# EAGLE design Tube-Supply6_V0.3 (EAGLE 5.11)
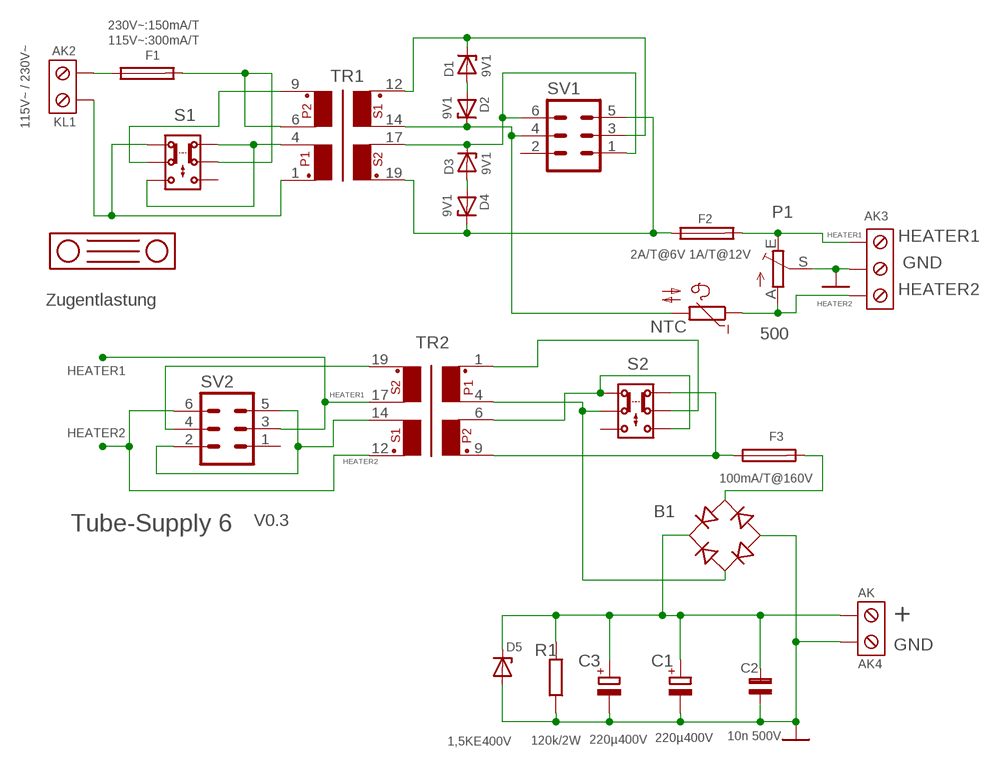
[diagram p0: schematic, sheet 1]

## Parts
AK  AK4  KL2RM7,5  [KL2RM7,5]
AK2  KL1  KLEMME2RM5  [KLEMME2]
AK3  KLEMME3STANDART  [KLEMME3]
B1  1000V/1A  DBL209G  [DB]
C1  220µ400V  CPOL-EUE10-25  [EB25D]
C2  10n 500V  C5B4,5E  [C5B4,5A]
C3  220µ400V  CPOL-EUE10-25  [EB25D]
D1  9V1  1N5333  [C1702-15]
D2  9V1  1N5333  [C1702-15]
D3  9V1  1N5333  [C1702-15]
D4  9V1  1N5333  [C1702-15]
D5  1,5KE400V  1N5333  [C1702-15]
F1  230V~:150mA/T  SH22,5A  [SH22,5A]
F2  2A/T@6V 1A/T@12V  SH22,5A  [SH22,5A]
F3  100mA/T@160V  SH22,5A  [SH22,5A]
NTC  NTC644B  [N644B]
P1  500  TRIM_EU-LI15  [LI15]
R1  120k/2W  R-EU_0411/12  [0411/12]
S1  X2200  [X2200]
S2  X2200  [X2200]
SV1  MA03-2  [MA03-2]
SV2  MA03-2  [MA03-2]
TR1  2x115V / 2x6V-2x2.5A  UI39X17DS45057  [UI39_24VA]
TR2  2x115V / 2x6V-2x2.5A  UI39X17DS45057  [UI39_24VA]
U$2  KAZU0442  [KAZU0442]

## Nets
+: AK.1 B1.+ C1.+ C2.2 C3.+ D5.C R1.2
GND: AK3.2 AK.2 B1.- C1.- C2.1 C3.- D5.A P1.S R1.1
HEATER1: AK3.3 F2.2 P1.E SV2.3 TR2.17
HEATER2: AK3.1 NTC.1 P1.A SV2.6 TR2.12
N$1: D3.A D4.A
N$3: D1.A D2.A
N$4: AK2.1 F1.1
N$5: F1.2 S1.1.2 TR1.6
N$6: S1.2.2 TR1.9
N$7: D1.C SV1.3 TR1.12
N$8: D2.C NTC.2 SV1.4 TR1.14
N$10: D4.C F2.1 SV1.5 TR1.19
N$11: D3.C SV1.1 SV1.6 TR1.17
N$12: SV2.4 TR2.19
N$13: SV2.2 SV2.5 TR2.14
N$17: B1.AC2 F3.2
N$18: AK2.2 S1.2.1 TR1.1
N$24: S1.1.1 S1.2.3 TR1.4
P1_1: S2.1.2 TR2.1
P1_4: B1.AC1 S2.2.2 TR2.4
P2_6: S2.1.3 S2.2.1 TR2.6
P2_9: F3.1 S2.1.1 TR2.9
Unconnected: S1.1.3 S2.2.3 SV1.2 SV2.1

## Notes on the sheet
- 115V~:300mA/T
- 115V~ / 230V~
- Zugentlastung
- V0.3
- Tube-Supply 6

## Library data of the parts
AK = VERBINDE:KL2RM7,5
AK2 = VERBINDE:KLEMME2
AK3 = VERBINDE:KLEMME3
B1 = rectifier:DB?*G: Single Phase 1.0 AMP Glass Passivated Bridge Rectifier Taiwan Semiconductor Co.,Ltd. - TSC Source: http://www.taiwansemi.com/TSCbig5/ezcatfiles/cust/img/img/db101g.pdf http://www.ts.com.tw/db/pictures/modules/PDT/PDT060207001/DBLS201G.pdf
C1 C3 = rcl:CPOL-EU: POLARIZED CAPACITOR, European symbol
C2 = CAP-Kondensatoren:C5B4,5E
D1-D5 = diode:1N5333: Z DIODE
F1-F3 = fuse:SH22,5A: FUSE HOLDER; MPN: 0031.7701.11; OC_FARNELL: unknown; OC_NEWARK: 04F1224
NTC = ptc-ntc:NTC644B: PHILIPS NTC; OC_FARNELL: unknown; OC_NEWARK: unknown
P1 = Potentiometer:TRIM_EU-: POTENTIOMETER
R1 = rcl:R-EU_: RESISTOR, European symbol
S1 S2 = switch:X2200
SV1 SV2 = con-lstb:MA03-2: PIN HEADER; OC_FARNELL: unknown; OC_NEWARK: unknown
TR1 TR2 = trafo:UI39X17DS45057
U$2 = MB:KAZU0442

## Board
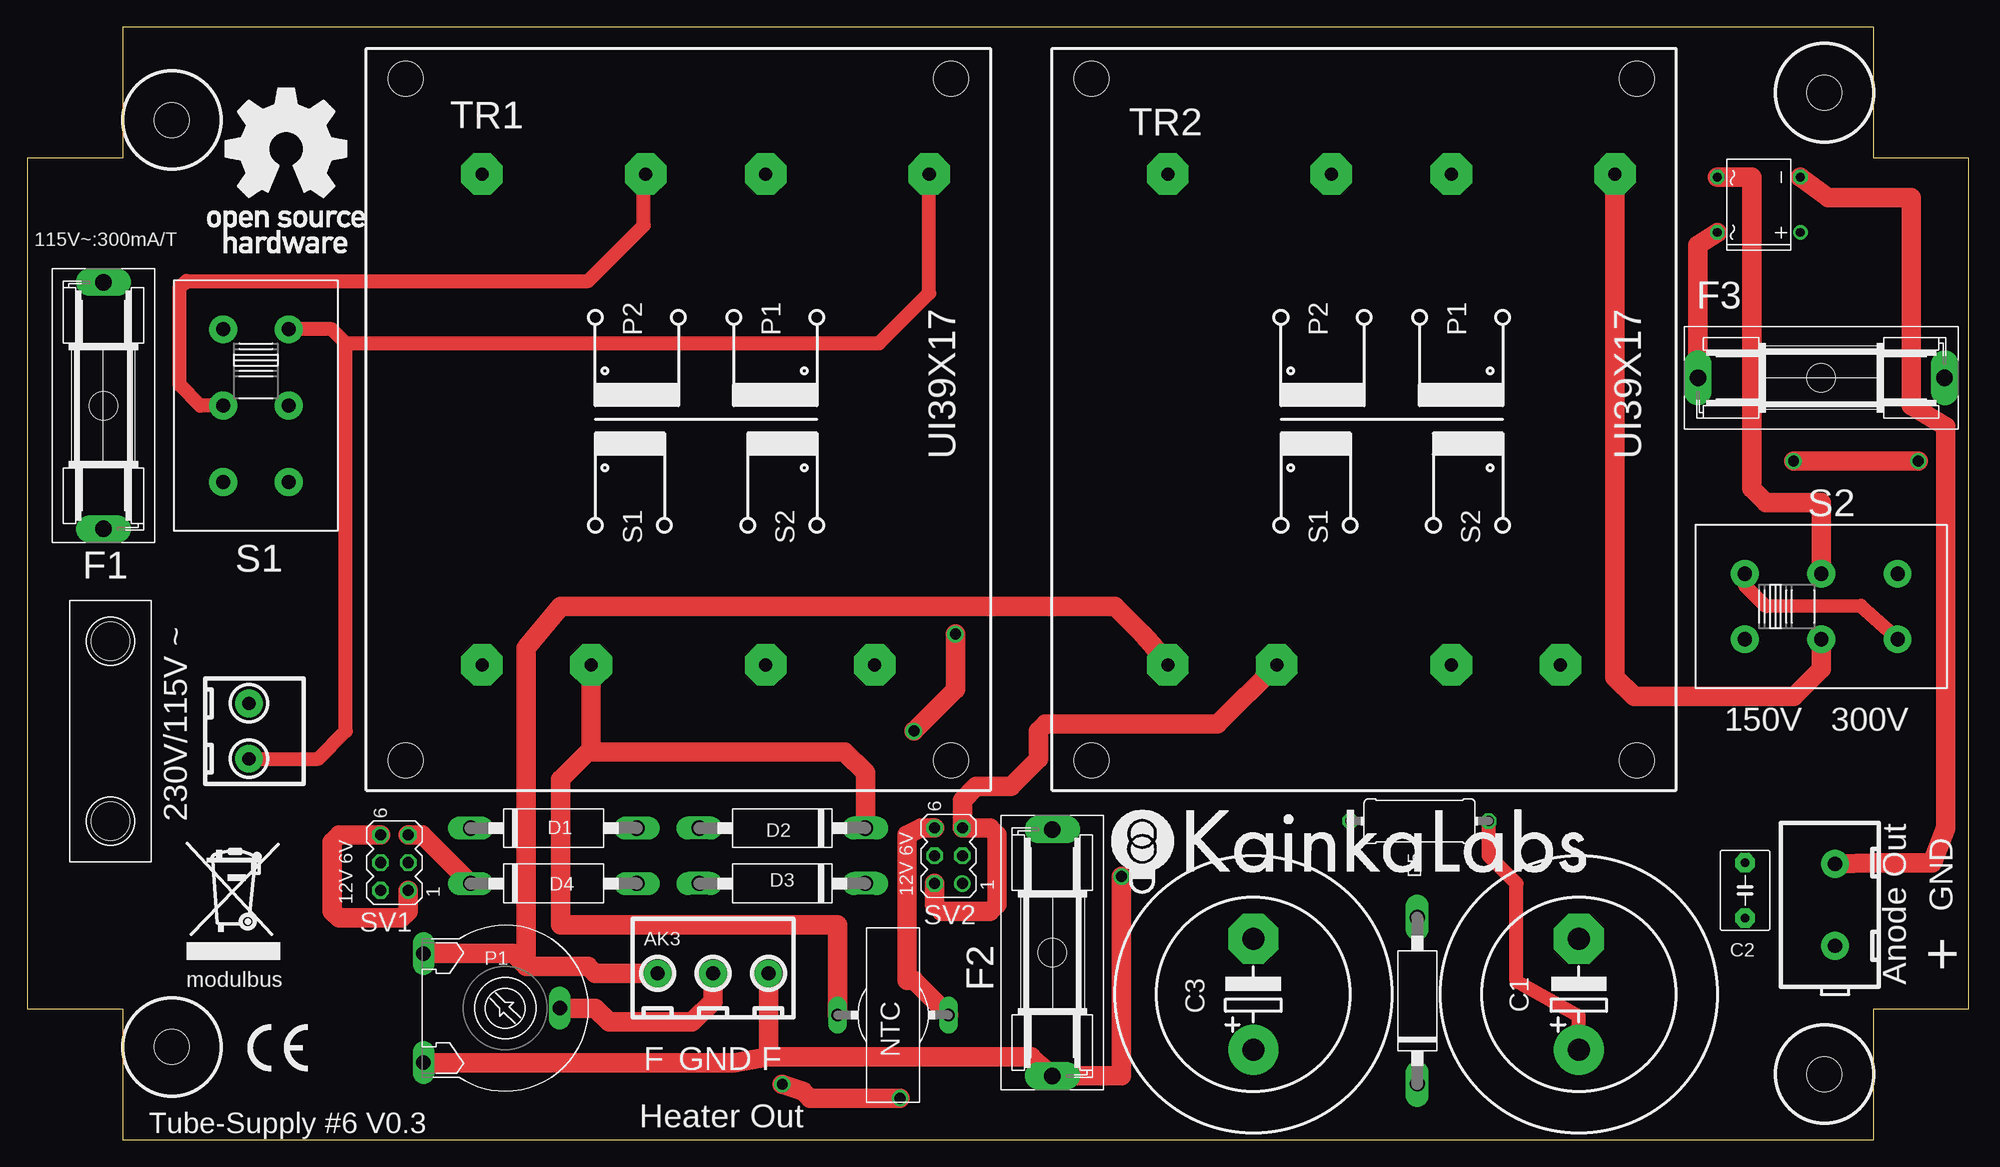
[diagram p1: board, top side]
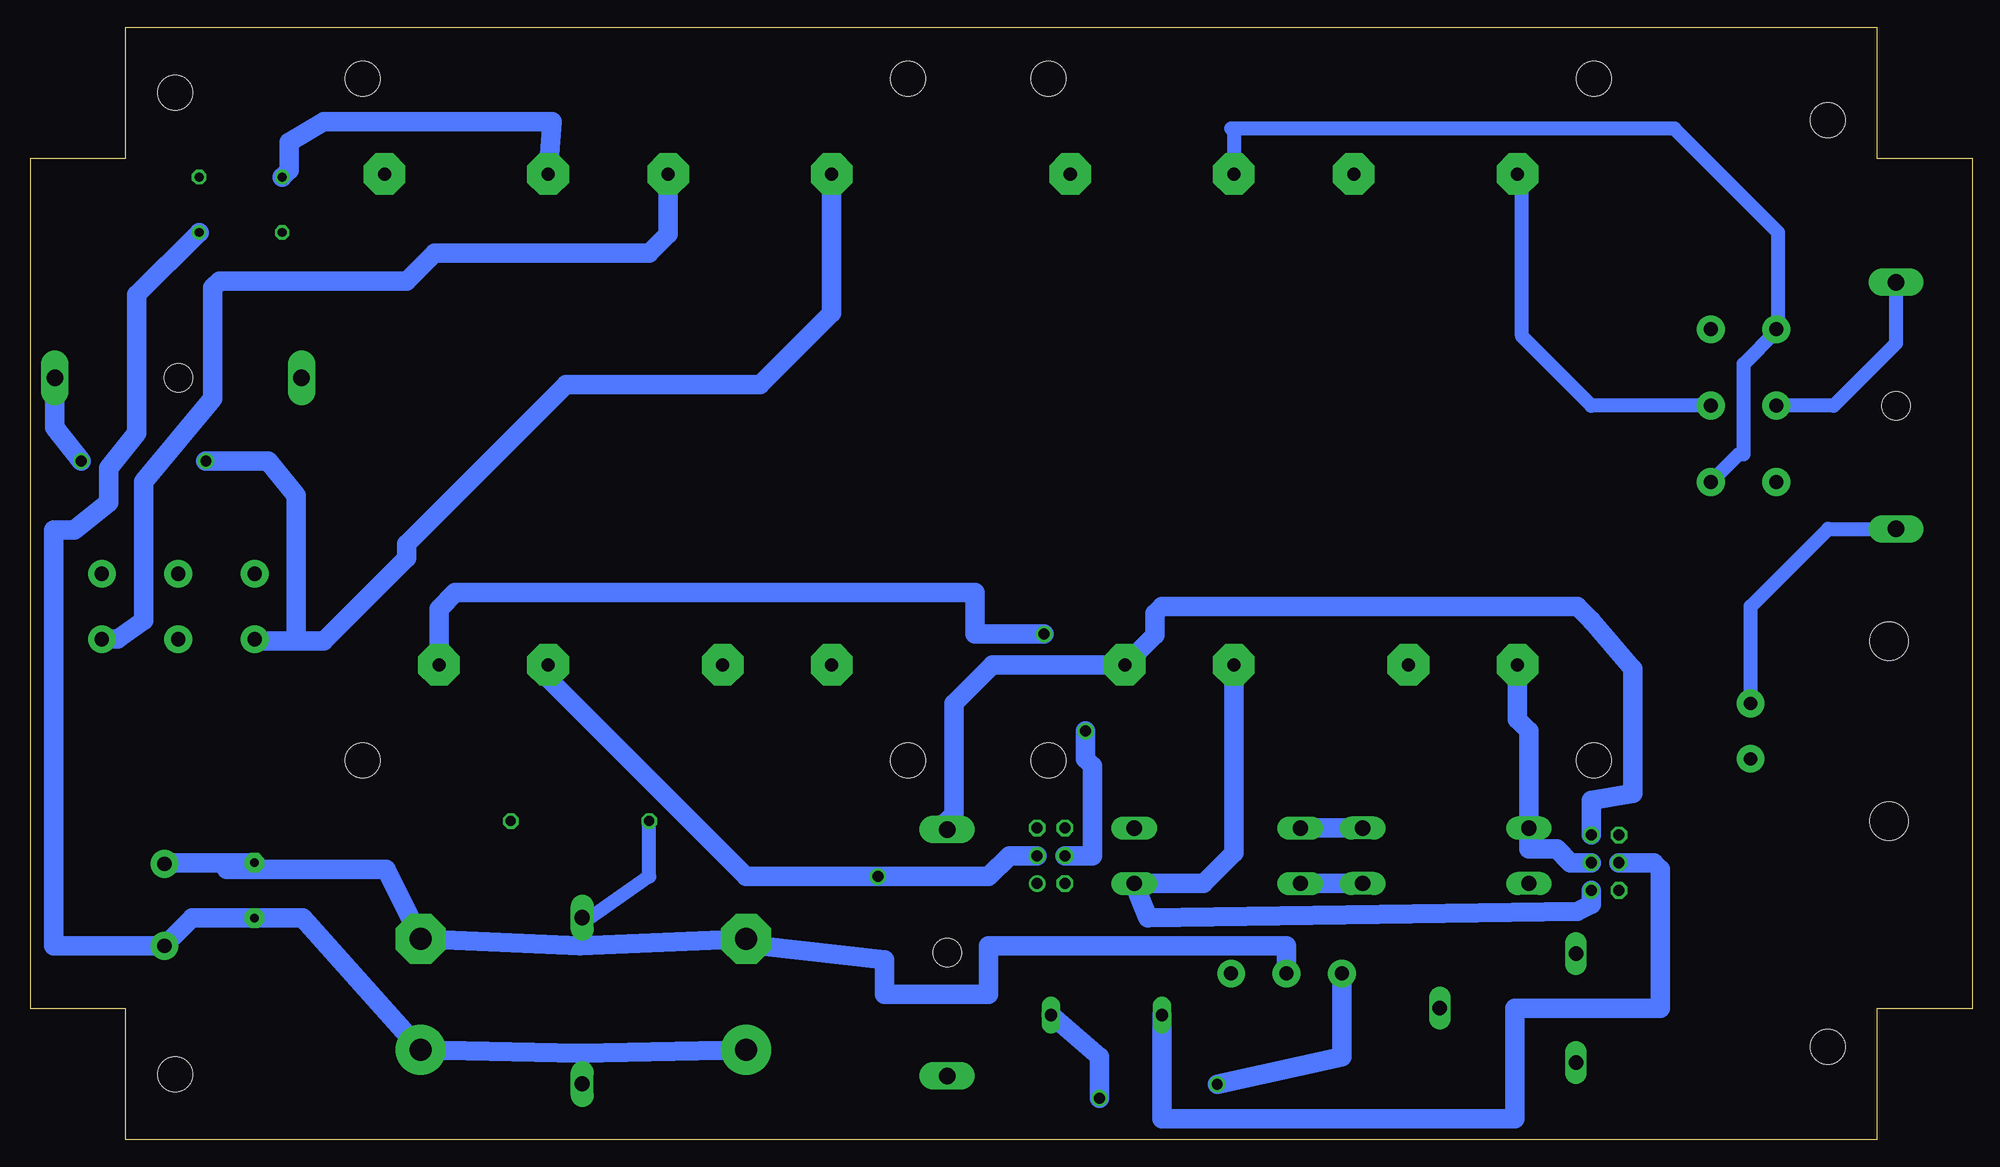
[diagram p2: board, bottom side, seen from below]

Size 178 x 102 mm. Coordinates in mm from the lower left corner, seen from the top.
Copper layers (1*16): Top 0.035mm / dielectric 1.5mm / Bottom 0.035mm
Design rules "default": minimum track width 10mil, minimum drill 23mil, track to track 8mil, track to pad 8mil, pad to pad 8mil, via to via 8mil, smd to smd 8mil, copper to edge 40mil, drill to drill 8mil, minimum pad ring 10mil, minimum via ring 8mil, stop-mask expansion 4mil, vias tented up to drill 0mil, thermal gap 20mil

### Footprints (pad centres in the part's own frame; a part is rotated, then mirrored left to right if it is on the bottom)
KL2RM7,5 = drill 1.3 pad 2.54 round: 1 0,0; 2 7.5,0
KLEMME2 = drill 1.2 pad 2.54 round: 1 0,0; 2 5.08,0
KLEMME3 = drill 1.3 pad 2.54 round: 1 0,0; 2 5.08,0; 3 10.16,0
DB = drill 0.813 round: + -2.54,-3.81 | drill 0.813 octagon: - 2.54,-3.81; AC1 2.54,3.81; AC2 -2.54,3.81
EB25D = drill 2.007 pad 4.597 round: + -5.08,0 | drill 2.007 pad 4.597 octagon: - 5.08,0
C5B4,5A = drill 0.813 pad 1.778 octagon: 1 -2.54,0; 2 2.54,0
C1702-15 = drill 1.397 long: A 7.62,0; C -7.62,0
SH22,5A = drill 1.5 pad 2.54 long: 1 -11.3,0; 2 11.3,0 | hole 2.6: 0,0
BO-E450 = hole 3.2: 13.25,8.5; 164.75,6; 13.25,93.5; 164.75,96
N644B = drill 1.118 long: 1 -5.08,0; 2 5.08,0
LI15 = drill 1.321 long: A -5,-7.5; E 5,-7.5; S 0,5
0411/12 = drill 0.914 octagon: 1 -6.35,0; 2 6.35,0
X2200 = drill 1.3 pad 2.54 round: 1.1 -7,-3; 1.2 0,-3; 1.3 7,-3; 2.1 -7,3; 2.2 0,3; 2.3 7,3
MA03-2 = drill 1.016 round: 1 -2.54,-1.27 | drill 1.016 octagon: 2 -2.54,1.27; 3 0,-1.27; 4 0,1.27; 5 2.54,-1.27; 6 2.54,1.27
UI39_24VA = drill 1.194 pad 3.81 octagon: 1 23,22.5; 4 8,22.5; 6 -3,22.5; 9 -18,22.5; 12 -18,-22.5; 14 -8,-22.5; 17 8,-22.5; 19 18,-22.5 | hole 3.2: -25,31.25; 25,31.25; 25,-31.25; -25,-31.25
KAZU0442 = hole 3.5: 0,0; 16.5,0

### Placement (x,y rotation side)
AK  165.74,17.78 90 top
AK2  20.32,40.01 270 top
AK3  57.78,15.24 0 top
B1  158.75,85.72 90 top
C1  142.24,13.34 90 top
C2  157.48,22.86 270 top
C3  112.39,13.34 90 top
D1  48.26,28.57 0 top
D2  69.22,28.57 180 top
D3  69.22,23.5 180 top
D4  48.26,23.5 0 top
D5  127.44,12.73 90 top
F1  6.99,67.31 90 top
F2  93.98,17.14 270 top
F3  164.47,69.85 180 top
GEHÄUSE  [BO-E450]  0,0 0 top
NTC  79.38,11.43 180 top
P1  43.81,12.06 270 top
R1  127.64,29.21 0 top
S1  20.95,67.31 270 top
S2  164.47,48.9 0 top
SV1  33.66,25.4 90 top
SV2  84.45,26.04 90 top
TR1  59.69,66.04 0 top
TR2  122.56,66.04 0 top
U$2  7.62,29.21 90 top
U$3  [KAINKALABS40MM]  99.36,22.55 0 top
U$4  [OSH15MM]  16.51,81.28 0 top
U$5  [EAR]  14.64,16.51 0 top
U$8  [CE6MM]  20.2,6.27 0 top

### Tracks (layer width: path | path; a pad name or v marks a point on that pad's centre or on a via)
+
  Top 1.27: R1.2 133.99,26.04 136.53,23.5 136.53,14.5 142.23,11.34 142.15,8.16 C1.+
  Bottom 1.27: D5.C 127.44,7.77 127.61,7.94
  Bottom 1.778: B1.+ 168.28,77.47 168.28,64.77 170.81,61.59 170.81,58.42 173.99,55.88 175.9,55.88 175.9,17.78 AK.1 163.19,20.32 C2.2 153.03,20.32 C1.+ 127.61,7.94 C3.+
GND
  Top 1.778: P1.S 52.07,12.06 53.34,10.79 60.96,10.79 62.87,12.7 AK3.2 | B1.- 165.1,86.36 172.72,86.36 172.72,67.31 175.9,65.41 175.9,28.57 174.62,25.4 169.43,25.4 AK.2
  Bottom 1.27: R1.1 121.28,24.13 127.64,19.68 | 127.64,19.68 127.64,20.16 D5.A | 127.64,19.68 127.64,17.78
  Bottom 1.778: AK3.2 62.87,17.78 90.17,17.78 90.17,13.34 99.69,13.34 99.69,16.51 111.12,17.78 C3.- 127.64,17.78 C1.- 145.41,24.77 160.02,24.77 C2.1 164.98,25.4 AK.2
HEATER1  (via drill 1)
  Top 1.778: 67.94,7.62 AK3.3 | 67.94,7.62 91.94,7.62 | 91.94,7.62 F2.2 100.33,5.84 100.33,10.79 v100.33,24.13 | P1.E 64.85,7.07 67.94,7.62 | 91.94,7.62 92.08,7.62
  Bottom 1.778: SV2.3 88.27,26.04 90.17,24.13 v100.33,24.13 112.39,24.13 131.44,43.18 130.91,43.18 TR2.17
HEATER2  (via drill 1)
  Top 1.778: SV2.6 81.92,28.57 80.64,27.94 80.64,14.61 81.28,14.61 NTC.1 | AK3.1 52.07,15.24 51.44,15.88 45.72,15.88 | 45.72,15.88 45.72,45.09 48.9,48.9 99.69,48.9 102.23,46.35 103.09,45.39 TR2.12 | P1.A 44.53,17.07 45.72,15.88 | v69.22,5.08 71.12,4.45 71.75,3.81 v80.01,3.81
  Bottom 1.778: AK3.1 57.78,7.62 v69.22,5.08 | v80.01,3.81 80.01,7.62 NTC.1
N$1
  Bottom 1.778: D4.A D3.A
N$3
  Bottom 1.778: D1.A D2.A
N$4
  Bottom 1.27: F1.1 13.21,56.01 20.32,48.9 AK2.1
N$5
  Top 1.27: S1.1.2 15.88,67.31 13.97,69.22 13.97,78.11 14.61,78.74 51.44,78.74 56.52,83.82 56.52,88.36 TR1.6
  Bottom 1.27: F1.2 6.99,73.03 12.7,67.31 S1.1.2
N$6
  Bottom 1.27: S1.2.2 34.92,67.31 41.27,73.66 41.27,88.12 TR1.9
N$7
  Bottom 1.778: TR1.12 41.69,38.52 40.64,37.47 D1.C 40.64,26.67 38.1,26.67 36.83,25.4 SV1.3
N$8
  Top 1.778: 51.69,35.81 TR1.14 | 51.69,35.81 48.9,33.02 48.9,19.68 74.3,19.68 NTC.2 | D2.C 76.83,33.66 74.93,35.56 51.95,35.56 51.69,35.81
  Bottom 1.778: SV1.4 29.21,25.4 28.57,24.77 28.57,12.06 41.91,12.06 41.91,1.91 74.3,1.91 NTC.2
N$10
  Top 1.778: SV1.5 36.2,27.94 D4.C
  Bottom 1.778: SV1.5 34.92,31.11 31.11,31.75 31.11,43.18 34.92,47.62 36.2,48.9 74.3,48.9 74.93,48.26 74.93,46.3 TR1.19 89.81,43.54 93.34,40.01 93.34,29.84 94.61,28.57 94.11,28.57 F2.1
N$11
  Top 1.778: SV1.6 28.57,27.94 27.94,27.3 27.94,20.95 28.57,20.32 34.29,20.32 34.92,20.95 SV1.1
  Bottom 1.778: SV1.1 34.92,21.59 36.2,20.95 75.56,20.32 D3.C 70.48,23.5 67.69,26.29 TR1.17
N$12  (via drill 1)
  Top 1.778: v85.09,46.35 85.09,41.27 v81.28,37.47
  Bottom 1.778: TR2.19 140.56,48.67 139.06,50.16 91.44,50.16 91.44,46.35 v85.09,46.35 | v81.28,37.47 81.28,34.92 80.64,34.29 80.64,26.04 SV2.4
N$13
  Top 1.778: SV2.2 83.19,21.59 83.82,20.95 88.27,20.95 88.9,21.59 88.9,27.94 88.27,28.57 SV2.5 85.72,31.11 87,32.38 90.17,32.38 92.71,34.92 92.71,37.47 93.34,38.1 109.11,38.1 TR2.14
N$17
  Top 1.778: F3.2 153.16,82.05 B1.AC2
N$18
  Top 1.27: S1.2.1 27.93,74.31 29.21,73.03 | 29.21,73.03 29.21,37.47 26.67,34.92 AK2.2 | TR1.1 82.69,77.61 78.11,73.03 29.21,73.03
  Bottom 1.27: 19.68,34.92 AK2.2
N$24
  Bottom 1.27: TR1.4 67.69,92.45 67.94,92.71 27.3,92.71 17.78,83.19 17.78,74.48 S1.1.1 17.95,74.12 20.95,71.12 20.95,62.87 21.4,62.87 S1.2.3
P1_1
  Top 1.778: TR2.1 145.56,42.41 147.32,40.64 161.93,40.64 164.47,43.18 S2.1.2
P1_4
  Top 1.778: B1.AC1 158.12,88.27 158.12,64.77 158.12,59.69 159.38,58.42 164.47,58.42 S2.2.2
  Bottom 1.778: TR2.4 130.18,93.34 151.13,93.34 154.31,91.44 154.31,88.9 B1.AC1
P2_6
  Top 1.27: S2.2.1 157.47,50.81 159.38,48.9 168.11,48.94 S2.1.3
  Bottom 1.778: TR2.6 119.56,83.01 121.28,81.28 140.97,81.28 143.51,78.74 160.66,78.74 161.29,78.11 161.29,67.94 167.64,60.33 167.64,47.62 170,45.9 S2.1.3
P2_9  (via drill 1)
  Top 1.778: v161.93,62.23 v173.35,62.23
  Bottom 1.778: TR2.9 104.56,75.78 111.12,69.22 128.91,69.22 143.51,54.61 143.51,53.34 151.13,45.72 153.67,45.72 | 153.67,45.72 157.29,45.72 S2.1.1 | F3.1 175.76,65.28 v173.35,62.23 | v161.93,62.23 156.21,62.23 153.67,59.05 153.67,45.72

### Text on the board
tPlace: 115V~:300mA/T | 230V/115V ~ | modulbus | Tube-Supply #6 V0.3
tNames: F3 | S2 | S1 | F1 | 150V 300V | 12V 6V | 12V 6V | GND | SV2 | SV1 | + | F2 | Anode Out | F | GND | F | Heater Out
tValues: 50mA/T@320V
